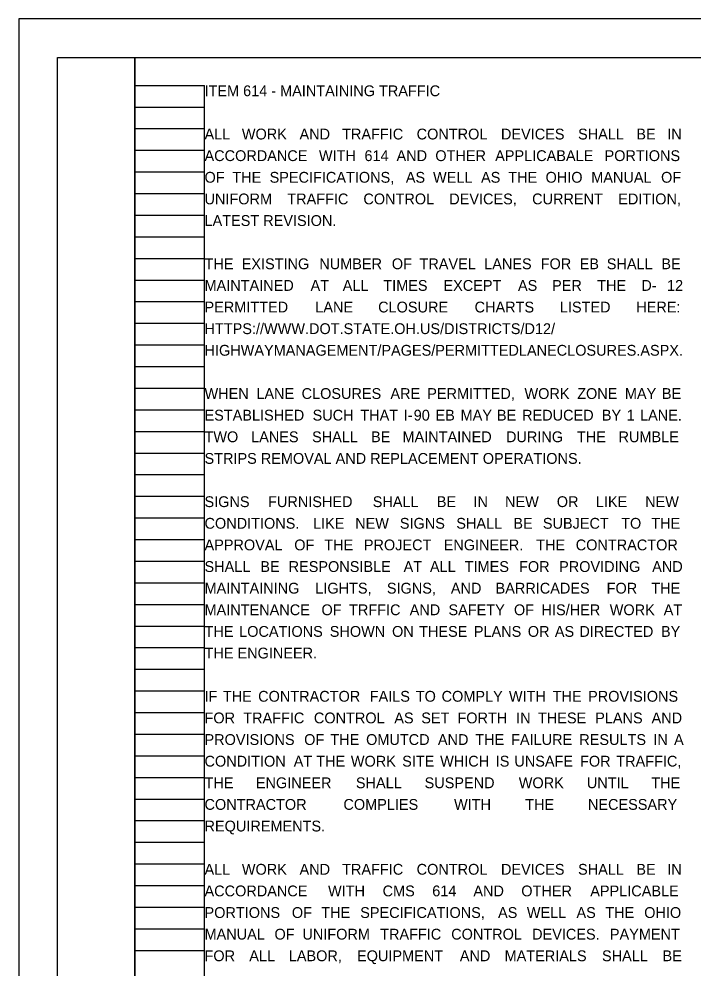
# Model space of a CAD drawing. Extents: x 0 to 34, y 0 to 22.
# Drawn here: x 0 to 8.72, y 9.71 to 22 of the extents above; entities that cross this region are included whole.
import ezdxf

# ---------------------------------------------------------------- set-up
doc = ezdxf.new("R2010")
doc.units = 0
for name, color, linetype in [('SH_Border', 7, 'Continuous'), ('SH_Cut_Line', 7, 'Continuous'), ('SH_Data', 7, 'Continuous'), ('SH_Text', 7, 'Continuous')]:
    doc.layers.add(name, color=color, linetype=linetype)

msp = doc.modelspace()

# ---------------------------------------------------------------- linework, layer by layer
at = {"layer": 'SH_Border'}
for points in [[(0.5, 21.5), (1.5, 21.5), (1.5, 0.5), (0.5, 0.5)], [(1.5, 21.5), (33.5, 21.5), (33.5, 0.5), (1.5, 0.5)]]:
    msp.add_lwpolyline(points, close=True, dxfattribs=at)
at = {"layer": 'SH_Cut_Line'}
msp.add_lwpolyline([(0, 0), (34, 0), (34, 22), (0, 22)], close=True, dxfattribs=at)
at = {"layer": 'SH_Data'}
for p, q in [((1.5, 0.98), (1.5, 21.14)), ((1.5, 21.14), (2.4, 21.14)), ((2.4, 0.98), (2.4, 21.14)), ((1.5, 20.86), (2.4, 20.86)), ((1.5, 20.58), (2.4, 20.58)), ((1.5, 20.3), (2.4, 20.3)), ((1.5, 20.02), (2.4, 20.02)), ((1.5, 19.74), (2.4, 19.74)), ((1.5, 19.46), (2.4, 19.46)), ((1.5, 19.18), (2.4, 19.18)), ((1.5, 18.9), (2.4, 18.9)), ((1.5, 18.62), (2.4, 18.62)), ((1.5, 18.34), (2.4, 18.34)), ((1.5, 18.06), (2.4, 18.06)), ((1.5, 17.78), (2.4, 17.78)), ((1.5, 17.5), (2.4, 17.5)), ((1.5, 17.22), (2.4, 17.22)), ((1.5, 16.94), (2.4, 16.94)), ((1.5, 16.66), (2.4, 16.66)), ((1.5, 16.38), (2.4, 16.38)), ((1.5, 16.1), (2.4, 16.1)), ((1.5, 15.82), (2.4, 15.82)), ((1.5, 15.54), (2.4, 15.54)), ((1.5, 15.26), (2.4, 15.26)), ((1.5, 14.98), (2.4, 14.98)), ((1.5, 14.7), (2.4, 14.7)), ((1.5, 14.42), (2.4, 14.42)), ((1.5, 14.14), (2.4, 14.14)), ((1.5, 13.86), (2.4, 13.86)), ((1.5, 13.58), (2.4, 13.58)), ((1.5, 13.3), (2.4, 13.3)), ((1.5, 13.02), (2.4, 13.02)), ((1.5, 12.74), (2.4, 12.74)), ((1.5, 12.46), (2.4, 12.46)), ((1.5, 12.18), (2.4, 12.18)), ((1.5, 11.9), (2.4, 11.9)), ((1.5, 11.62), (2.4, 11.62)), ((1.5, 11.34), (2.4, 11.34)), ((1.5, 11.06), (2.4, 11.06)), ((1.5, 10.78), (2.4, 10.78)), ((1.5, 10.5), (2.4, 10.5)), ((1.5, 10.22), (2.4, 10.22)), ((1.5, 9.94), (2.4, 9.94))]:
    msp.add_line(p, q, dxfattribs=at)

# ---------------------------------------------------------------- texts
at = {"layer": 'SH_Text'}
for s, p in [('ITEM 614 - MAINTAINING TRAFFIC', (2.4, 21)), ('ALL ', (2.4, 20.44)), ('WORK ', (2.883, 20.44)), ('AND ', (3.629, 20.44)), ('TRAFFIC ', (4.18, 20.44)), ('CONTROL ', (5.144, 20.44)), ('DEVICES ', (6.235, 20.44)), ('SHALL ', (7.232, 20.44)), ('BE ', (7.986, 20.44)), ('IN ', (8.386, 20.44)), ('ACCORDANCE ', (2.4, 20.16)), ('WITH ', (3.88, 20.16)), ('614 ', (4.469, 20.16)), ('AND ', (4.884, 20.16)), ('OTHER ', (5.386, 20.16)), ('APPLICABALE ', (6.16, 20.16)), ('PORTIONS ', (7.575, 20.16)), ('OF ', (2.4, 19.88)), ('THE ', (2.76, 19.88)), ('SPECIFICATIONS, ', (3.242, 19.88)), ('AS ', (5.004, 19.88)), ('WELL ', (5.356, 19.88)), ('AS ', (5.977, 19.88)), ('THE ', (6.329, 19.88)), ('OHIO ', (6.812, 19.88)), ('MANUAL ', (7.403, 19.88)), ('OF ', (8.306, 19.88)), ('UNIFORM ', (2.4, 19.6)), ('TRAFFIC ', (3.471, 19.6)), ('CONTROL ', (4.455, 19.6)), ('DEVICES, ', (5.566, 19.6)), ('CURRENT ', (6.638, 19.6)), ('EDITION, ', (7.752, 19.6)), ('LATEST REVISION.', (2.4, 19.32)), ('THE ', (2.4, 18.76)), ('EXISTING ', (2.881, 18.76)), ('NUMBER ', (3.885, 18.76)), ('OF ', (4.823, 18.76)), ('TRAVEL ', (5.181, 18.76)), ('LANES ', (6.018, 18.76)), ('FOR ', (6.749, 18.76)), ('EB ', (7.253, 18.76)), ('SHALL ', (7.604, 18.76)), ('BE ', (8.31, 18.76)), ('MAINTAINED ', (2.4, 18.48)), ('AT ', (3.772, 18.48)), ('ALL ', (4.188, 18.48)), ('TIMES ', (4.713, 18.48)), ('EXCEPT ', (5.491, 18.48)), ('AS ', (6.455, 18.48)), ('PER ', (6.896, 18.48)), ('THE ', (7.479, 18.48)), ('D-', (8.051, 18.48)), ('12 ', (8.383, 18.48)), ('PERMITTED ', (2.4, 18.2)), ('LANE ', (3.833, 18.2)), ('CLOSURE ', (4.646, 18.2)), ('CHARTS ', (5.894, 18.2)), ('LISTED ', (6.997, 18.2)), ('HERE: ', (7.985, 18.2)), ('HTTPS://WWW.DOT.STATE.OH.US/DISTRICTS/D12/', (2.4, 17.92)), ('HIGHWAYMANAGEMENT/PAGES/PERMITTEDLANECLOSURES.ASPX.', (2.4, 17.64)), ('WHEN ', (2.4, 17.08)), ('LANE ', (3.071, 17.08)), ('CLOSURES ', (3.656, 17.08)), ('ARE ', (4.805, 17.08)), ('PERMITTED, ', (5.281, 17.08)), ('WORK ', (6.539, 17.08)), ('ZONE ', (7.221, 17.08)), ('MAY ', (7.838, 17.08)), ('BE ', (8.317, 17.08)), ('ESTABLISHED ', (2.4, 16.8)), ('SUCH ', (3.798, 16.8)), ('THAT ', (4.416, 16.8)), ('I-', (4.977, 16.8)), ('90 ', (5.106, 16.8)), ('EB ', (5.388, 16.8)), ('MAY ', (5.713, 16.8)), ('BE ', (6.183, 16.8)), ('REDUCED ', (6.508, 16.8)), ('BY ', (7.54, 16.8)), ('1 ', (7.861, 16.8)), ('LANE. ', (8.034, 16.8)), ('TWO ', (2.4, 16.52)), ('LANES ', (3.003, 16.52)), ('SHALL ', (3.791, 16.52)), ('BE ', (4.554, 16.52)), ('MAINTAINED ', (4.961, 16.52)), ('DURING ', (6.3, 16.52)), ('THE ', (7.218, 16.52)), ('RUMBLE ', (7.756, 16.52)), ('STRIPS REMOVAL AND REPLACEMENT OPERATIONS.', (2.4, 16.24)), ('SIGNS ', (2.4, 15.68)), ('FURNISHED ', (3.222, 15.68)), ('SHALL ', (4.576, 15.68)), ('BE ', (5.405, 15.68)), ('IN ', (5.879, 15.68)), ('NEW ', (6.288, 15.68)), ('OR ', (6.957, 15.68)), ('LIKE ', (7.463, 15.68)), ('NEW ', (8.1, 15.68)), ('CONDITIONS. ', (2.4, 15.4)), ('LIKE ', (3.804, 15.4)), ('NEW ', (4.349, 15.4)), ('SIGNS ', (4.927, 15.4)), ('SHALL ', (5.657, 15.4)), ('BE ', (6.395, 15.4)), ('SUBJECT ', (6.777, 15.4)), ('TO ', (7.79, 15.4)), ('THE ', (8.18, 15.4)), ('APPROVAL ', (2.4, 15.12)), ('OF ', (3.561, 15.12)), ('THE ', (3.949, 15.12)), ('PROJECT ', (4.461, 15.12)), ('ENGINEER. ', (5.494, 15.12)), ('THE ', (6.69, 15.12)), ('CONTRACTOR ', (7.202, 15.12)), ('SHALL ', (2.4, 14.84)), ('BE ', (3.122, 14.84)), ('RESPONSIBLE ', (3.488, 14.84)), ('AT ', (4.975, 14.84)), ('ALL ', (5.316, 14.84)), ('TIMES ', (5.766, 14.84)), ('FOR ', (6.469, 14.84)), ('PROVIDING ', (6.987, 14.84)), ('AND ', (8.191, 14.84)), ('MAINTAINING ', (2.4, 14.56)), ('LIGHTS, ', (3.833, 14.56)), ('SIGNS, ', (4.759, 14.56)), ('AND ', (5.587, 14.56)), ('BARRICADES ', (6.165, 14.56)), ('FOR ', (7.602, 14.56)), ('THE ', (8.18, 14.56)), ('MAINTENANCE ', (2.4, 14.28)), ('OF ', (3.913, 14.28)), ('TRFFIC ', (4.27, 14.28)), ('AND ', (5.054, 14.28)), ('SAFETY ', (5.556, 14.28)), ('OF ', (6.403, 14.28)), ('HIS/HER ', (6.76, 14.28)), ('WORK ', (7.642, 14.28)), ('AT ', (8.34, 14.28)), ('THE ', (2.4, 14)), ('LOCATIONS ', (2.848, 14)), ('SHOWN ', (4.02, 14)), ('ON ', (4.826, 14)), ('THESE ', (5.176, 14)), ('PLANS ', (5.884, 14)), ('OR ', (6.582, 14)), ('AS ', (6.932, 14)), ('DIRECTED ', (7.249, 14)), ('BY ', (8.305, 14)), ('THE ENGINEER. ', (2.4, 13.72)), ('IF ', (2.4, 13.16)), ('THE ', (2.637, 13.16)), ('CONTRACTOR ', (3.094, 13.16)), ('FAILS ', (4.537, 13.16)), ('TO ', (5.133, 13.16)), ('COMPLY ', (5.467, 13.16)), ('WITH ', (6.338, 13.16)), ('THE ', (6.904, 13.16)), ('PROVISIONS ', (7.362, 13.16)), ('FOR ', (2.4, 12.88)), ('TRAFFIC ', (2.901, 12.88)), ('CONTROL ', (3.815, 12.88)), ('AS ', (4.855, 12.88)), ('SET ', (5.204, 12.88)), ('FORTH ', (5.672, 12.88)), ('IN ', (6.431, 12.88)), ('THESE ', (6.714, 12.88)), ('PLANS ', (7.454, 12.88)), ('AND ', (8.183, 12.88)), ('PROVISIONS ', (2.4, 12.6)), ('OF ', (3.689, 12.6)), ('THE ', (4.028, 12.6)), ('OMUTCD ', (4.49, 12.6)), ('AND ', (5.419, 12.6)), ('THE ', (5.903, 12.6)), ('FAILURE ', (6.366, 12.6)), ('RESULTS ', (7.248, 12.6)), ('IN ', (8.207, 12.6)), ('A ', (8.474, 12.6)), ('CONDITION ', (2.4, 12.32)), ('AT ', (3.554, 12.32)), ('THE ', (3.845, 12.32)), ('WORK ', (4.293, 12.32)), ('SITE ', (4.957, 12.32)), ('WHICH ', (5.448, 12.32)), ('IS ', (6.167, 12.32)), ('UNSAFE ', (6.408, 12.32)), ('FOR ', (7.258, 12.32)), ('TRAFFIC, ', (7.727, 12.32)), ('THE ', (2.4, 12.04)), ('ENGINEER ', (3.064, 12.04)), ('SHALL ', (4.358, 12.04)), ('SUSPEND ', (5.247, 12.04)), ('WORK ', (6.465, 12.04)), ('UNTIL ', (7.346, 12.04)), ('THE ', (8.18, 12.04)), ('CONTRACTOR ', (2.4, 11.76)), ('COMPLIES ', (4.197, 11.76)), ('WITH ', (5.628, 11.76)), ('THE ', (6.548, 11.76)), ('NECESSARY ', (7.36, 11.76)), ('REQUIREMENTS.', (2.4, 11.48)), ('ALL ', (2.4, 10.92)), ('WORK ', (2.883, 10.92)), ('AND ', (3.629, 10.92)), ('TRAFFIC ', (4.18, 10.92)), ('CONTROL ', (5.144, 10.92)), ('DEVICES ', (6.235, 10.92)), ('SHALL ', (7.232, 10.92)), ('BE ', (7.986, 10.92)), ('IN ', (8.386, 10.92)), ('ACCORDANCE ', (2.4, 10.64)), ('WITH ', (3.998, 10.64)), ('CMS ', (4.704, 10.64)), ('614 ', (5.346, 10.64)), ('AND ', (5.878, 10.64)), ('OTHER ', (6.498, 10.64)), ('APPLICABLE ', (7.39, 10.64)), ('PORTIONS ', (2.4, 10.36)), ('OF ', (3.53, 10.36)), ('THE ', (3.911, 10.36)), ('SPECIFICATIONS, ', (4.414, 10.36)), ('AS ', (6.197, 10.36)), ('WELL ', (6.57, 10.36)), ('AS ', (7.212, 10.36)), ('THE ', (7.585, 10.36)), ('OHIO ', (8.088, 10.36)), ('MANUAL ', (2.4, 10.08)), ('OF ', (3.305, 10.08)), ('UNIFORM ', (3.666, 10.08)), ('TRAFFIC ', (4.672, 10.08)), ('CONTROL ', (5.591, 10.08)), ('DEVICES. ', (6.638, 10.08)), ('PAYMENT ', (7.644, 10.08)), ('FOR ', (2.4, 9.8)), ('ALL ', (2.979, 9.8)), ('LABOR, ', (3.49, 9.8)), ('EQUIPMENT ', (4.373, 9.8)), ('AND ', (5.703, 9.8)), ('MATERIALS ', (6.282, 9.8)), ('SHALL ', (7.542, 9.8)), ('BE ', (8.325, 9.8))]:
    msp.add_text(s, height=0.14, dxfattribs=at).set_placement(p)

doc.saveas('drawing.dxf')
